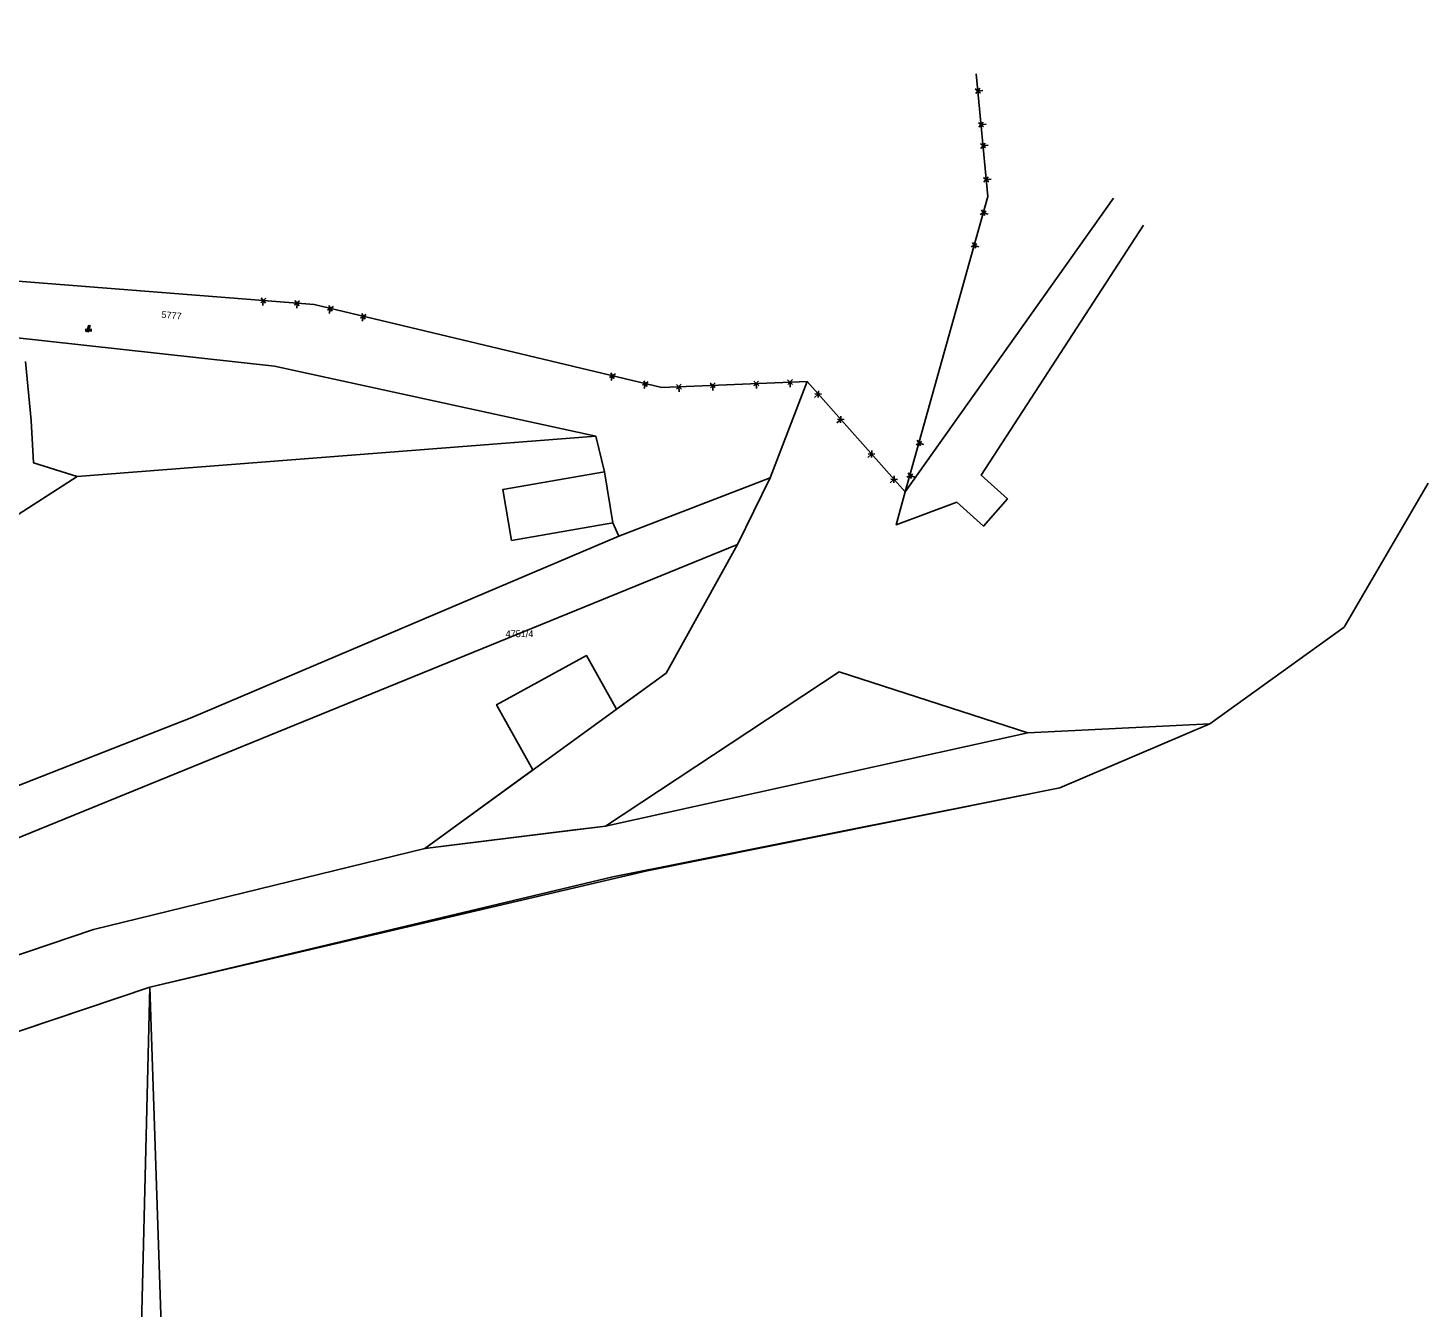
# Model space of a CAD drawing. Extents: x -439750 to -439180, y -1258684 to -1258308.
# Drawn here: x -439311.2 to -439228.6, y -1258422.2 to -1258346.7 of the extents above; entities that cross this region are included whole.
import ezdxf

# ---------------------------------------------------------------- set-up
doc = ezdxf.new("R2010")
doc.units = 0
doc.layers.add('KATASTER', color=7, linetype='Continuous')
doc.layers.add('UOV', color=7, linetype='Continuous')

# ---------------------------------------------------------------- blocks, each defined once
blk = doc.blocks.new('CESTA')
for p, q in [((-0.32, 0.8), (-1, 0.8)), ((-1, 0.4), (-0.46, 0.4)), ((0.1, 2), (-0.6, 0)), ((-0.1, 0), (0.5, 2)), ((0.02, 0.4), (1, 0.4)), ((1, 0.8), (0.14, 0.8))]:
    blk.add_line(p, q)
blk = doc.blocks.new('2072')
for p, q in [((-4.3, 0.7), (-5.7, -0.7)), ((-5.7, 0.7), (-4.3, -0.7)), ((-5, 0), (-5, -1.5)), ((4.3, 0.7), (5.7, -0.7)), ((5.7, 0.7), (4.3, -0.7)), ((5, 0), (5, -1.5))]:
    blk.add_line(p, q)

msp = doc.modelspace()

# ---------------------------------------------------------------- linework, layer by layer
at = {"layer": 'KATASTER'}
for points in [[(-439255.265, -1258349.384), (-439254.59, -1258356.61), (-439259.45, -1258374.06), (-439265.25, -1258367.53), (-439273.81, -1258367.89), (-439294.34, -1258362.99), (-439319.08, -1258361.05), (-439328.04, -1258358.53), (-439357.98, -1258347.42), (-439361.22, -1258351.62), (-439365.48, -1258348.34), (-439391.19, -1258328.53), (-439415.15, -1258317.05), (-439445.45, -1258309.53), (-439455.48, -1258307.79), (-439478.63, -1258311.39), (-439488.88, -1258312.99), (-439507.94, -1258320.79), (-439517.56, -1258326.72), (-439510.66, -1258363.93), (-439529.05, -1258372.98), (-439583.01, -1258405.44)], [(-439583.01, -1258405.44), (-439529.05, -1258372.98), (-439510.66, -1258363.93), (-439517.56, -1258326.72), (-439507.94, -1258320.79), (-439488.88, -1258312.99), (-439478.63, -1258311.39), (-439455.48, -1258307.79), (-439445.45, -1258309.53), (-439415.15, -1258317.05), (-439391.19, -1258328.53), (-439365.48, -1258348.34), (-439361.22, -1258351.62), (-439357.98, -1258347.42), (-439328.04, -1258358.53), (-439319.08, -1258361.05), (-439294.34, -1258362.99), (-439273.81, -1258367.89), (-439265.25, -1258367.53), (-439259.45, -1258374.06), (-439254.59, -1258356.61), (-439255.265, -1258349.384)], [(-439316.1, -1258393.08), (-439301.55, -1258387.38), (-439276.35, -1258376.67), (-439267.42, -1258373.23), (-439269.36, -1258377.15), (-439315.05, -1258395.8)], [(-439320.71, -1258462.43), (-439302.65, -1258444.27), (-439304.03, -1258403.29), (-439276.7, -1258396.78), (-439250.33, -1258391.52), (-439241.48, -1258387.75), (-439233.56, -1258382.03), (-439228.61, -1258373.536)], [(-439342.07, -1258411.63), (-439307.35, -1258399.88), (-439287.8, -1258395.11), (-439277.15, -1258393.78), (-439263.36, -1258384.67), (-439252.22, -1258388.27), (-439241.48, -1258387.75), (-439250.33, -1258391.52), (-439276.7, -1258396.78), (-439304.03, -1258403.29), (-439334.89, -1258413.69)]]:
    msp.add_lwpolyline(points, dxfattribs=at)
for points in [[(-439267.42, -1258373.23), (-439276.35, -1258376.67), (-439276.71, -1258375.89), (-439277.2, -1258372.87), (-439277.72, -1258370.76), (-439296.68, -1258366.63), (-439319.2, -1258364.15), (-439328.88, -1258361.61), (-439351.95, -1258352.84), (-439361.22, -1258351.62), (-439357.98, -1258347.42), (-439328.04, -1258358.53), (-439319.08, -1258361.05), (-439294.34, -1258362.99), (-439273.81, -1258367.89), (-439265.25, -1258367.53)], [(-439360.22, -1258395.64), (-439354.32, -1258378.96), (-439333.16, -1258382.13), (-439318.87, -1258379.92), (-439316.73, -1258378.56), (-439308.31, -1258373.15), (-439277.72, -1258370.76), (-439277.2, -1258372.87), (-439283.2, -1258373.92), (-439282.68, -1258376.92), (-439276.71, -1258375.89), (-439276.35, -1258376.67), (-439301.55, -1258387.38), (-439316.1, -1258393.08), (-439324.92, -1258395.23), (-439331.05, -1258396.01)], [(-439269.36, -1258377.15), (-439273.57, -1258384.75), (-439276.5, -1258386.89), (-439278.27, -1258383.72), (-439283.57, -1258386.62), (-439281.42, -1258390.47), (-439287.8, -1258395.11), (-439307.35, -1258399.88), (-439342.07, -1258411.63), (-439355.32, -1258412.49), (-439390.34, -1258418.93), (-439368.16, -1258411.35), (-439367.83, -1258398.64), (-439329.65, -1258398.85), (-439324.38, -1258397.9), (-439315.05, -1258395.8)]]:
    msp.add_lwpolyline(points, close=True, dxfattribs=at)
at = {"layer": 'UOV'}
for points in [[(-439247.166, -1258356.723), (-439259.45, -1258374.06), (-439259.99, -1258375.99), (-439256.42, -1258374.67), (-439254.83, -1258376.07), (-439253.43, -1258374.47), (-439254.98, -1258373.06), (-439245.405, -1258358.318)], [(-439319.08, -1258361.05), (-439294.34, -1258362.99), (-439273.81, -1258367.89), (-439265.25, -1258367.53), (-439267.42, -1258373.23), (-439269.36, -1258377.15), (-439273.57, -1258384.75), (-439287.8, -1258395.11), (-439307.35, -1258399.88), (-439342.07, -1258411.63)], [(-439228.61, -1258373.536), (-439233.56, -1258382.03), (-439241.48, -1258387.75), (-439252.22, -1258388.27), (-439263.36, -1258384.67), (-439277.15, -1258393.78), (-439279.12, -1258394.03), (-439287.8, -1258395.11), (-439273.57, -1258384.75), (-439269.36, -1258377.15), (-439267.42, -1258373.23), (-439265.25, -1258367.53), (-439273.81, -1258367.89), (-439294.34, -1258362.99), (-439319.08, -1258361.05)], [(-439316.1, -1258393.08), (-439301.55, -1258387.38), (-439276.35, -1258376.67), (-439276.71, -1258375.89), (-439277.2, -1258372.87), (-439277.72, -1258370.76), (-439308.31, -1258373.15), (-439310.89, -1258372.34), (-439311.02, -1258369.84), (-439311.36, -1258366.36)], [(-439311.36, -1258366.36), (-439311.02, -1258369.84), (-439310.89, -1258372.34), (-439308.31, -1258373.15), (-439277.72, -1258370.76), (-439277.2, -1258372.87), (-439276.71, -1258375.89), (-439276.35, -1258376.67), (-439301.55, -1258387.38), (-439316.1, -1258393.08)], [(-439241.48, -1258387.75), (-439233.56, -1258382.03), (-439228.61, -1258373.536)], [(-439320.71, -1258462.43), (-439304.86, -1258436.82), (-439304.03, -1258403.29), (-439274.68, -1258396.43), (-439250.33, -1258391.52), (-439241.48, -1258387.75)]]:
    msp.add_lwpolyline(points, dxfattribs=at)
msp.add_lwpolyline([(-439304.03, -1258403.29), (-439341.3, -1258415.85), (-439354.3, -1258417.7), (-439355.78, -1258417.92), (-439355.89, -1258417.18), (-439368.25, -1258419.92), (-439368.12, -1258414.84), (-439355.32, -1258412.49), (-439342.07, -1258411.63), (-439307.35, -1258399.88), (-439287.8, -1258395.11), (-439279.12, -1258394.03), (-439277.15, -1258393.78), (-439252.22, -1258388.27), (-439241.48, -1258387.75), (-439250.33, -1258391.52), (-439274.68, -1258396.43)], close=True, dxfattribs=at)

# ---------------------------------------------------------------- block references
at = {"layer": 'KATASTER'}
for p, xscale, yscale, rotation in [((-439255.079, -1258351.376), 0.2, 0.19999999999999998, 95.34017700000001), ((-439254.776, -1258354.619), 0.2, 0.19999999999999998, 95.34017700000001), ((-439255.127, -1258358.537), 0.2, 0.19999999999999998, 74.42721800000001), ((-439296.334, -1258362.834), 0.2, 0.19999999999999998, -4.479688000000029), ((-439292.395, -1258363.454), 0.2, 0.19999999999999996, -13.417830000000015), ((-439275.755, -1258367.426), 0.2, 0.19999999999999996, -13.417830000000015), ((-439267.248, -1258367.614), 0.2, 0.19999999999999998, 2.4064229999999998), ((-439271.812, -1258367.806), 0.2, 0.19999999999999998, 2.4064229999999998), ((-439263.922, -1258369.025), 0.20000000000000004, 0.2, -48.36825500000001), ((-439260.778, -1258372.565), 0.20000000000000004, 0.2, -48.36825500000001), ((-439258.913, -1258372.133), 0.2, 0.19999999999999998, 74.42721800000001)]:
    msp.add_blockref('2072', p, dxfattribs=dict(at, xscale=xscale, yscale=yscale, rotation=rotation))
at = {"layer": 'KATASTER', "xscale": 0.2, "yscale": 0.20000000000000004}
msp.add_blockref('CESTA', (-439307.65, -1258364.62), dxfattribs=at)

# ---------------------------------------------------------------- texts
at = {"layer": 'KATASTER'}
msp.add_text('5777', height=0.4, rotation=354.604, dxfattribs=at).set_placement((-439303.356, -1258363.777))
at = {"layer": 'UOV'}
msp.add_text('4751/4', height=0.4, dxfattribs=at).set_placement((-439283.034, -1258382.63))

doc.saveas('drawing.dxf')
